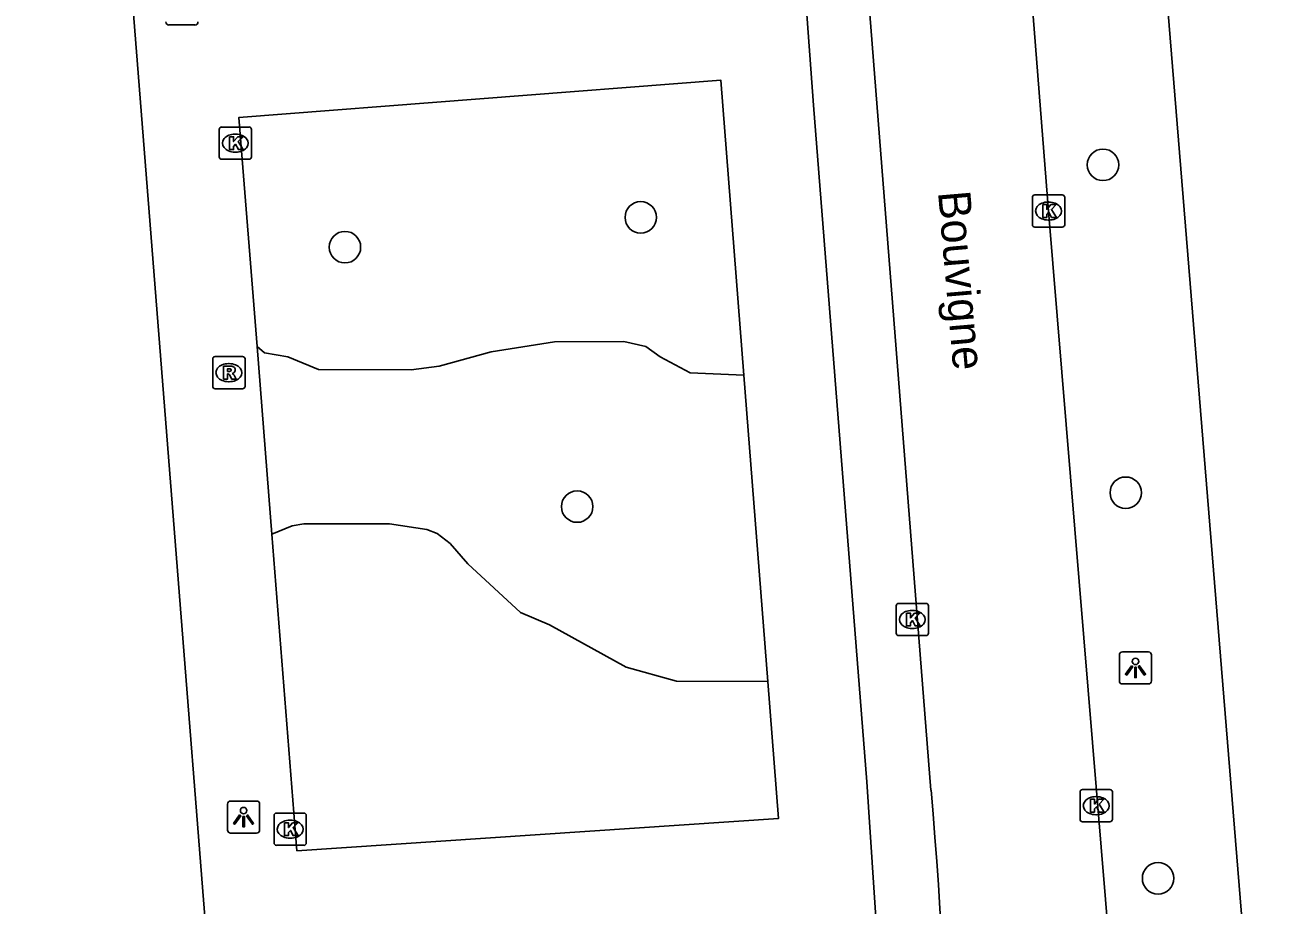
# Model space of a CAD drawing. Extents: x 157793 to 159380, y 380882 to 382313.
# Drawn here: x 158207.48 to 158246.22, y 381165.2 to 381192.48 of the extents above; entities that cross this region are included whole.
import ezdxf

# ---------------------------------------------------------------- set-up
doc = ezdxf.new("R2010")
doc.units = 0
for name, color, linetype in [('IMGEO_Boom', 7, 'Continuous'), ('IMGEO_Groenvoorziening', 7, 'Continuous'), ('IMGEO_Kolk', 7, 'Continuous'), ('IMGEO_Lichtpunt', 7, 'Continuous'), ('IMGEO_Openbare_ruimte_label', 7, 'Continuous'), ('IMGEO_Rijbaan_lokaal_gesloten', 7, 'Continuous'), ('IMGEO_Rioolput', 7, 'Continuous'), ('IMGEO_Voetpad_open', 7, 'Continuous')]:
    doc.layers.add(name, color=color, linetype=linetype)

msp = doc.modelspace()

# ---------------------------------------------------------------- linework, layer by layer
at = {"layer": 'IMGEO_Boom'}
for centre in [(158240.912, 381188.145), (158226.577, 381186.515), (158217.4, 381185.593), (158241.62, 381177.978), (158224.604, 381177.551), (158242.622, 381166.026)]:
    msp.add_circle(centre, 0.489, dxfattribs=at)
at = {"layer": 'IMGEO_Groenvoorziening'}
for points in [[(158214.676, 381182.509), (158214.91, 381182.317), (158215.635, 381182.188), (158216.58, 381181.796), (158219.452, 381181.788), (158220.326, 381181.905), (158221.941, 381182.35), (158223.896, 381182.654), (158226.055, 381182.666), (158226.73, 381182.518), (158227.174, 381182.191), (158228.107, 381181.701), (158229.773, 381181.625)], [(158215.137, 381176.692), (158215.76, 381176.955), (158216.127, 381177.017), (158218.78, 381177.012), (158219.946, 381176.844), (158220.258, 381176.714), (158220.665, 381176.401), (158221.211, 381175.78), (158222.851, 381174.271), (158223.747, 381173.885), (158226.124, 381172.568), (158227.689, 381172.134), (158230.517, 381172.124)]]:
    msp.add_lwpolyline(points, dxfattribs=at)
at = {"layer": 'IMGEO_Kolk'}
for p, q in [((158213.502, 381188.392), (158213.502, 381189.244)), ((158213.577, 381189.318), (158214.429, 381189.318)), ((158214.503, 381189.244), (158214.503, 381188.392)), ((158213.99, 381189.098), (158214.015, 381189.098)), ((158214.013, 381188.538), (158213.988, 381188.538)), ((158214.429, 381188.318), (158213.577, 381188.318)), ((158238.723, 381186.287), (158238.723, 381187.139)), ((158238.798, 381187.213), (158239.65, 381187.213)), ((158239.211, 381186.993), (158239.236, 381186.993)), ((158239.724, 381187.139), (158239.724, 381186.287)), ((158239.65, 381186.213), (158238.798, 381186.213)), ((158239.234, 381186.433), (158239.209, 381186.433)), ((158234.572, 381174.55), (158235.424, 381174.55)), ((158234.497, 381173.624), (158234.497, 381174.476)), ((158234.985, 381174.33), (158235.01, 381174.33)), ((158235.498, 381174.476), (158235.498, 381173.624)), ((158235.008, 381173.77), (158234.983, 381173.77)), ((158235.424, 381173.55), (158234.572, 381173.55)), ((158240.277, 381168.778), (158241.129, 381168.778)), ((158240.202, 381167.852), (158240.202, 381168.704)), ((158240.69, 381168.558), (158240.715, 381168.558)), ((158241.203, 381168.704), (158241.203, 381167.852)), ((158215.202, 381167.122), (158215.202, 381167.974)), ((158215.277, 381168.048), (158216.129, 381168.048)), ((158216.203, 381167.974), (158216.203, 381167.122)), ((158240.713, 381167.998), (158240.688, 381167.998)), ((158215.69, 381167.828), (158215.715, 381167.828)), ((158241.129, 381167.778), (158240.277, 381167.778)), ((158215.713, 381167.268), (158215.688, 381167.268)), ((158216.129, 381167.048), (158215.277, 381167.048))]:
    msp.add_line(p, q, dxfattribs=at)
for points in [[(158213.502, 381188.392), (158213.502, 381189.244)], [(158213.577, 381189.318), (158214.429, 381189.318)], [(158214.503, 381189.244), (158214.503, 381188.392)], [(158213.823, 381189.018), (158213.946, 381189.018), (158213.946, 381188.867), (158214.076, 381189.018), (158214.24, 381189.018), (158214.094, 381188.867), (158214.247, 381188.618), (158214.095, 381188.618), (158214.01, 381188.782), (158213.946, 381188.715), (158213.946, 381188.618), (158213.823, 381188.618), (158213.823, 381189.018)], [(158214.429, 381188.318), (158213.577, 381188.318)], [(158238.723, 381186.287), (158238.723, 381187.139)], [(158238.798, 381187.213), (158239.65, 381187.213)], [(158239.044, 381186.913), (158239.167, 381186.913), (158239.167, 381186.762), (158239.297, 381186.913), (158239.461, 381186.913), (158239.315, 381186.762), (158239.468, 381186.513), (158239.316, 381186.513), (158239.231, 381186.677), (158239.167, 381186.61), (158239.167, 381186.513), (158239.044, 381186.513), (158239.044, 381186.913)], [(158239.724, 381187.139), (158239.724, 381186.287)], [(158239.65, 381186.213), (158238.798, 381186.213)], [(158234.572, 381174.55), (158235.424, 381174.55)], [(158234.497, 381173.624), (158234.497, 381174.476)], [(158234.818, 381174.25), (158234.941, 381174.25), (158234.941, 381174.099), (158235.071, 381174.25), (158235.235, 381174.25), (158235.089, 381174.099), (158235.242, 381173.85), (158235.09, 381173.85), (158235.005, 381174.014), (158234.941, 381173.947), (158234.941, 381173.85), (158234.818, 381173.85), (158234.818, 381174.25)], [(158235.498, 381174.476), (158235.498, 381173.624)], [(158235.424, 381173.55), (158234.572, 381173.55)], [(158240.277, 381168.778), (158241.129, 381168.778)], [(158240.202, 381167.852), (158240.202, 381168.704)], [(158240.523, 381168.478), (158240.646, 381168.478), (158240.646, 381168.327), (158240.776, 381168.478), (158240.94, 381168.478), (158240.794, 381168.327), (158240.947, 381168.078), (158240.795, 381168.078), (158240.71, 381168.242), (158240.646, 381168.175), (158240.646, 381168.078), (158240.523, 381168.078), (158240.523, 381168.478)], [(158241.203, 381168.704), (158241.203, 381167.852)], [(158215.202, 381167.122), (158215.202, 381167.974)], [(158215.277, 381168.048), (158216.129, 381168.048)], [(158216.203, 381167.974), (158216.203, 381167.122)], [(158215.523, 381167.748), (158215.646, 381167.748), (158215.646, 381167.597), (158215.776, 381167.748), (158215.94, 381167.748), (158215.794, 381167.597), (158215.947, 381167.348), (158215.795, 381167.348), (158215.71, 381167.512), (158215.646, 381167.445), (158215.646, 381167.348), (158215.523, 381167.348), (158215.523, 381167.748)], [(158241.129, 381167.778), (158240.277, 381167.778)], [(158216.129, 381167.048), (158215.277, 381167.048)]]:
    msp.add_lwpolyline(points, dxfattribs=at)
for centre, start, end in [((158213.579, 381189.242), 91.552, 178.448), ((158213.579, 381189.242), 91.552, 178.448), ((158214.427, 381189.242), 1.552, 88.448), ((158214.427, 381189.242), 1.552, 88.448), ((158213.579, 381188.394), 181.552, 268.448), ((158213.579, 381188.394), 181.552, 268.448), ((158214.427, 381188.394), 271.552, 358.448), ((158214.427, 381188.394), 271.552, 358.448), ((158238.8, 381187.137), 91.552, 178.448), ((158238.8, 381187.137), 91.552, 178.448), ((158239.648, 381187.137), 1.552, 88.448), ((158239.648, 381187.137), 1.552, 88.448), ((158238.8, 381186.289), 181.552, 268.448), ((158238.8, 381186.289), 181.552, 268.448), ((158239.648, 381186.289), 271.552, 358.448), ((158239.648, 381186.289), 271.552, 358.448), ((158234.574, 381174.474), 91.552, 178.448), ((158234.574, 381174.474), 91.552, 178.448), ((158235.422, 381174.474), 1.552, 88.448), ((158235.422, 381174.474), 1.552, 88.448), ((158234.574, 381173.626), 181.552, 268.448), ((158234.574, 381173.626), 181.552, 268.448), ((158235.422, 381173.626), 271.552, 358.448), ((158235.422, 381173.626), 271.552, 358.448), ((158240.279, 381168.702), 91.552, 178.448), ((158240.279, 381168.702), 91.552, 178.448), ((158241.127, 381168.702), 1.552, 88.448), ((158241.127, 381168.702), 1.552, 88.448), ((158215.279, 381167.972), 91.552, 178.448), ((158215.279, 381167.972), 91.552, 178.448), ((158216.127, 381167.972), 1.552, 88.448), ((158216.127, 381167.972), 1.552, 88.448), ((158240.279, 381167.854), 181.552, 268.448), ((158240.279, 381167.854), 181.552, 268.448), ((158241.127, 381167.854), 271.552, 358.448), ((158241.127, 381167.854), 271.552, 358.448), ((158215.279, 381167.124), 181.552, 268.448), ((158215.279, 381167.124), 181.552, 268.448), ((158216.127, 381167.124), 271.552, 358.448), ((158216.127, 381167.124), 271.552, 358.448)]:
    msp.add_arc(centre, 0.0765, start, end, dxfattribs=at)
for centre, major_axis, ratio, start_param, end_param in [((158213.989, 381188.818), (-0.387, 0.002), 0.722429, 4.712389, 7.853982), ((158214.014, 381188.818), (-0.39, 0.002), 0.717154, 1.570796, 4.712389), ((158239.21, 381186.713), (-0.387, 0.002), 0.722429, 4.712389, 7.853982), ((158239.235, 381186.713), (-0.39, 0.002), 0.717154, 1.570796, 4.712389), ((158234.984, 381174.05), (-0.387, 0.002), 0.722429, 4.712389, 7.853982), ((158235.009, 381174.05), (-0.39, 0.002), 0.717154, 1.570796, 4.712389), ((158240.689, 381168.278), (-0.387, 0.002), 0.722429, 4.712389, 7.853982), ((158240.714, 381168.278), (-0.39, 0.002), 0.717154, 1.570796, 4.712389), ((158215.689, 381167.548), (-0.387, 0.002), 0.722429, 4.712389, 7.853982), ((158215.714, 381167.548), (-0.39, 0.002), 0.717154, 1.570796, 4.712389)]:
    msp.add_ellipse(centre, major_axis=major_axis, ratio=ratio, start_param=start_param, end_param=end_param, dxfattribs=at)
at = {"layer": 'IMGEO_Lichtpunt'}
for p, q in [((158211.941, 381192.481), (158212.749, 381192.481)), ((158211.941, 381192.481), (158212.749, 381192.481)), ((158242.324, 381173.048), (158241.516, 381173.048)), ((158242.324, 381173.048), (158241.516, 381173.048)), ((158241.422, 381172.953), (158241.422, 381172.146)), ((158241.422, 381172.953), (158241.422, 381172.146)), ((158242.418, 381172.146), (158242.418, 381172.953)), ((158242.418, 381172.146), (158242.418, 381172.953)), ((158241.516, 381172.052), (158242.324, 381172.052)), ((158241.516, 381172.052), (158242.324, 381172.052)), ((158213.759, 381168.327), (158213.759, 381167.52)), ((158213.759, 381168.327), (158213.759, 381167.52)), ((158214.661, 381168.422), (158213.853, 381168.422)), ((158214.661, 381168.422), (158213.853, 381168.422)), ((158214.755, 381167.52), (158214.755, 381168.327)), ((158214.755, 381167.52), (158214.755, 381168.327)), ((158213.853, 381167.426), (158214.661, 381167.426)), ((158213.853, 381167.426), (158214.661, 381167.426))]:
    msp.add_line(p, q, dxfattribs=at)
for points in [[(158241.796, 381172.617), (158241.835, 381172.589), (158241.647, 381172.327), (158241.609, 381172.354), (158241.796, 381172.617)], [(158242.008, 381172.589), (158242.046, 381172.616), (158242.233, 381172.354), (158242.194, 381172.326), (158242.008, 381172.589)], [(158241.898, 381172.569), (158241.945, 381172.569), (158241.945, 381172.247), (158241.898, 381172.247), (158241.898, 381172.569)], [(158214.133, 381167.991), (158214.172, 381167.963), (158213.984, 381167.701), (158213.946, 381167.728), (158214.133, 381167.991)], [(158214.235, 381167.943), (158214.282, 381167.943), (158214.282, 381167.621), (158214.235, 381167.621), (158214.235, 381167.943)], [(158214.345, 381167.963), (158214.383, 381167.99), (158214.57, 381167.728), (158214.531, 381167.7), (158214.345, 381167.963)]]:
    msp.add_lwpolyline(points, dxfattribs=at)
for centre in [(158241.921, 381172.751), (158214.258, 381168.125)]:
    msp.add_circle(centre, 0.0994, dxfattribs=at)
for centre, start, end in [((158211.941, 381192.575), 180, 270), ((158211.941, 381192.575), 180, 270), ((158212.749, 381192.575), 270, 0), ((158212.749, 381192.575), 270, 360), ((158241.516, 381172.953), 90, 180), ((158241.516, 381172.953), 90, 180), ((158242.324, 381172.953), 0, 90), ((158242.324, 381172.953), 0, 90), ((158241.516, 381172.146), 180, 270), ((158241.516, 381172.146), 180, 270), ((158242.324, 381172.146), 270, 0), ((158242.324, 381172.146), 270, 360), ((158213.853, 381168.327), 90, 180), ((158213.853, 381168.327), 90, 180), ((158214.661, 381168.327), 0, 90), ((158214.661, 381168.327), 0, 90), ((158213.853, 381167.52), 180, 270), ((158213.853, 381167.52), 180, 270), ((158214.661, 381167.52), 270, 0), ((158214.661, 381167.52), 270, 360)]:
    msp.add_arc(centre, 0.0946, start, end, dxfattribs=at)
at = {"layer": 'IMGEO_Rijbaan_lokaal_gesloten'}
for points in [[(158234.402, 381247.964), (158239.224, 381186.713), (158242.086, 381152.138)], [(158235.578, 381168.754), (158229.383, 381247.511)]]:
    msp.add_lwpolyline(points, dxfattribs=at)
msp.add_arc((158087.871, 381155.723), 148.281, 355.95897, 5.04149, dxfattribs=at)
at = {"layer": 'IMGEO_Rioolput'}
for p, q in [((158213.301, 381181.276), (158213.301, 381182.128)), ((158213.376, 381182.202), (158214.228, 381182.202)), ((158213.789, 381181.982), (158213.814, 381181.982)), ((158214.302, 381182.128), (158214.302, 381181.276)), ((158214.228, 381181.202), (158213.376, 381181.202)), ((158213.812, 381181.422), (158213.787, 381181.422))]:
    msp.add_line(p, q, dxfattribs=at)
for points in [[(158213.301, 381181.276), (158213.301, 381182.128)], [(158213.376, 381182.202), (158214.228, 381182.202)], [(158213.89, 381181.9), (158213.638, 381181.902), (158213.638, 381181.502)], [(158214.302, 381182.128), (158214.302, 381181.276)], [(158213.638, 381181.502), (158213.762, 381181.502), (158213.762, 381181.664), (158213.773, 381181.664)], [(158213.816, 381181.821), (158213.762, 381181.821), (158213.762, 381181.74)], [(158213.762, 381181.74), (158213.814, 381181.74)], [(158213.82, 381181.635), (158213.891, 381181.502), (158214.031, 381181.502), (158213.966, 381181.628)], [(158214.228, 381181.202), (158213.376, 381181.202)]]:
    msp.add_lwpolyline(points, dxfattribs=at)
for centre, radius, start, end in [((158213.378, 381182.126), 0.0765, 91.552, 178.448), ((158213.378, 381182.126), 0.0765, 91.552, 178.448), ((158213.889, 381181.79), 0.109, 350.3612, 89.416), ((158214.226, 381182.126), 0.0765, 1.552, 88.448), ((158214.226, 381182.126), 0.0765, 1.552, 88.448), ((158213.772, 381181.611), 0.0533, 26.0293, 88.6989), ((158213.798, 381181.929), 0.19, 274.7715, 282.9687), ((158213.822, 381181.725), 0.0964, 77.0061, 93.1865), ((158213.836, 381181.782), 0.0378, 276.6634, 79.6772), ((158213.887, 381181.79), 0.112, 277.5842, 350.9817), ((158213.871, 381181.575), 0.108, 29.5134, 73.7905), ((158213.378, 381181.278), 0.0765, 181.552, 268.448), ((158213.378, 381181.278), 0.0765, 181.552, 268.448), ((158214.226, 381181.278), 0.0765, 271.552, 358.448), ((158214.226, 381181.278), 0.0765, 271.552, 358.448)]:
    msp.add_arc(centre, radius, start, end, dxfattribs=at)
for centre, major_axis, ratio, start_param, end_param in [((158213.788, 381181.702), (-0.387, 0.002), 0.722429, 4.712389, 7.853982), ((158213.813, 381181.702), (-0.39, 0.002), 0.717154, 1.570796, 4.712389)]:
    msp.add_ellipse(centre, major_axis=major_axis, ratio=ratio, start_param=start_param, end_param=end_param, dxfattribs=at)
at = {"layer": 'IMGEO_Voetpad_open'}
for points in [[(158217.503, 381108.594), (158207.836, 381230.9), (158200.897, 381318.677)], [(158233.919, 381164.021), (158233.583, 381169.013), (158231.932, 381189.994), (158231.568, 381194.931), (158231.398, 381196.904), (158230.978, 381202.013), (158230.209, 381211.929), (158229.833, 381216.97), (158228.942, 381227.915), (158228.532, 381232.988), (158227.776, 381242.87), (158227.355, 381247.965), (158227, 381252.838)], [(158246.217, 381152.476), (158241.546, 381209.865), (158238.203, 381252.426)], [(158214.676, 381182.509), (158214.114, 381189.613), (158229.056, 381190.771), (158229.773, 381181.625)], [(158215.137, 381176.692), (158214.676, 381182.509)], [(158229.773, 381181.625), (158230.517, 381172.124)], [(158230.517, 381172.124), (158230.849, 381167.88), (158215.914, 381166.88), (158215.137, 381176.692)]]:
    msp.add_lwpolyline(points, dxfattribs=at)

# ---------------------------------------------------------------- texts
at = {"layer": 'IMGEO_Openbare_ruimte_label'}
msp.add_text('Bouvigne', height=1, rotation=274.935, dxfattribs=at).set_placement((158235.794, 381187.303))

doc.saveas('drawing.dxf')
